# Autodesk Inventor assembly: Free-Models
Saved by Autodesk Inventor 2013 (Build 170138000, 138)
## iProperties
Created: 2021-02
Part Number: Free-Models
Document SubType Name: Assembly
Designer: Fede
Author: Fede
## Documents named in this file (3)
- C:\0000 FEDE\16GB\0000 INTERIOR\DE_TMP_BAS\BAS_DTON - demora conexion al energizar\pcb\BOR\turn on\Imported Components\BAS_DTON\Free-Models.iam
- C:\0000 FEDE\16GB\0000 INTERIOR\DE_TMP_BAS\BAS_DTON - demora conexion al energizar\pcb\BOR\turn on\Imported Components\BAS_DTON\jump.iam
- C:\0000 FEDE\16GB\0000 INTERIOR\DE_TMP_BAS\BAS_DTON - demora conexion al energizar\pcb\BOR\turn on\Imported Components\BAS_DTON\pin4x1.iam
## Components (2 placed, 2 different names)
1. jump:1 [sub-assembly]
2. pin4x1:1 [sub-assembly]
